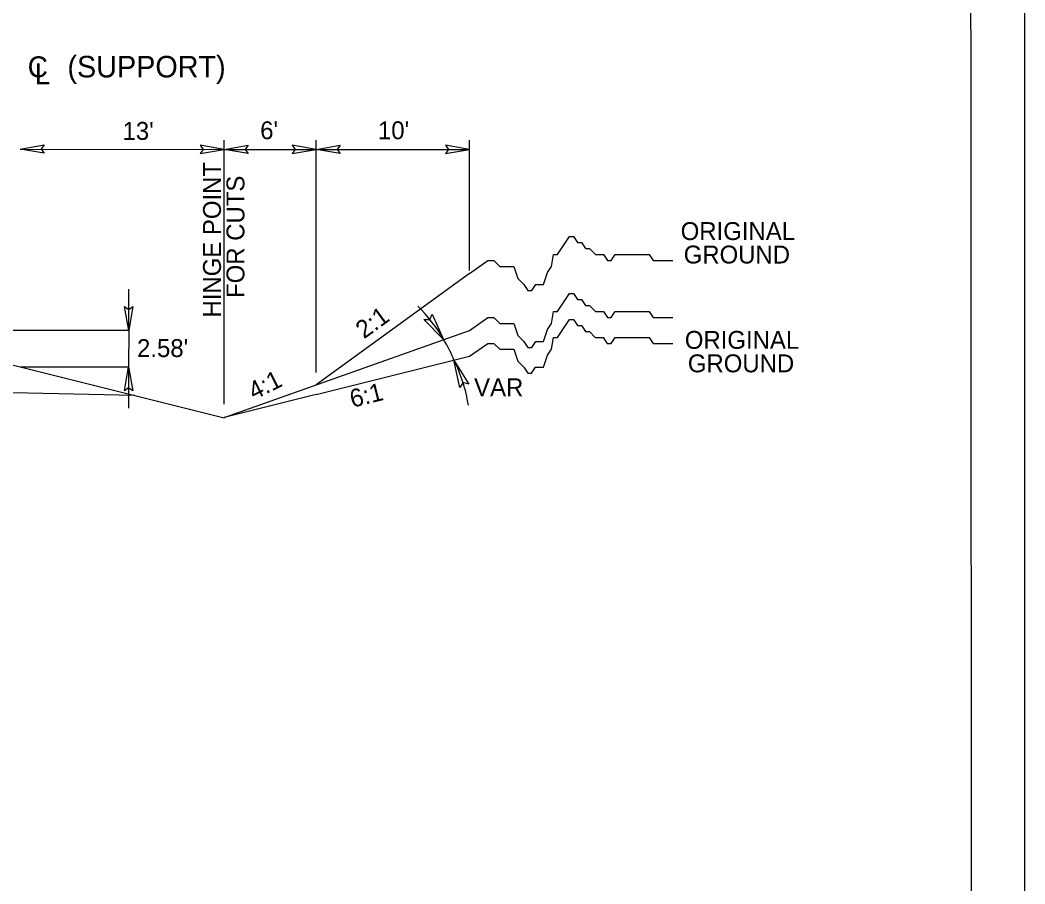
# Model space of a CAD drawing. Extents: x 1727387 to 1728895, y 539219 to 540208.
# Drawn here: x 1727645.2 to 1727723.8, y 539453.8 to 539521.4 of the extents above; entities that cross this region are included whole.
import ezdxf

# ---------------------------------------------------------------- set-up
doc = ezdxf.new("R2010")
doc.units = 0
for name, color, linetype in [('Default', 7, 'Continuous'), ('Overhead Sheet Border', 7, 'Continuous'), ('Prop Dimension Text', 7, 'Continuous'), ('Sheet Plot Border Outside CELL', 7, 'Continuous'), ('Typical Hinge Slope Interstate CELL', 7, 'Continuous'), ('Typical Pavement Slope CELL', 7, 'Continuous'), ('Typical Pavement Slope Information CELL', 7, 'Continuous'), ('Typical Text Centerline CELL', 7, 'Continuous')]:
    doc.layers.add(name, color=color, linetype=linetype)

msp = doc.modelspace()

# ---------------------------------------------------------------- linework, layer by layer
at = {"layer": 'Default'}
for p, q in [((1727645.155, 539511.289), (1727661.125, 539511.259)), ((1727661.126, 539511.259), (1727668.331, 539511.259)), ((1727661.133, 539491.314), (1727661.133, 539511.998)), ((1727668.331, 539511.259), (1727680.34, 539511.259)), ((1727668.339, 539493.807), (1727668.339, 539511.998)), ((1727680.347, 539501.785), (1727680.347, 539511.998)), ((1727653.656, 539497.076), (1727653.656, 539500.314)), ((1727653.649, 539497.076), (1727481.192, 539497.076)), ((1727653.656, 539497.076), (1727653.649, 539494.248)), ((1727645.155, 539494.248), (1727653.649, 539494.248)), ((1727653.649, 539494.248), (1727653.649, 539491.011))]:
    msp.add_line(p, q, dxfattribs=at)
for points in [[(1727647.034, 539510.966), (1727645.158, 539511.289), (1727647.044, 539511.623), (1727646.804, 539511.289)], [(1727659.258, 539510.937), (1727661.133, 539511.26), (1727659.247, 539511.593), (1727659.487, 539511.26)], [(1727663.009, 539510.937), (1727661.133, 539511.26), (1727663.019, 539511.593), (1727662.78, 539511.26)], [(1727666.463, 539510.937), (1727668.339, 539511.26), (1727666.453, 539511.593), (1727666.692, 539511.26)], [(1727670.214, 539510.937), (1727668.339, 539511.26), (1727670.225, 539511.593), (1727669.985, 539511.26)], [(1727678.464, 539510.936), (1727680.34, 539511.259), (1727678.454, 539511.592), (1727678.694, 539511.259)], [(1727653.984, 539498.951), (1727653.656, 539497.076), (1727653.327, 539498.963), (1727653.66, 539498.723)], [(1727677.404, 539498.363), (1727678.314, 539496.367), (1727676.772, 539497.947), (1727677.245, 539497.935)], [(1727679.588, 539492.617), (1727679.122, 539494.76), (1727680.294, 539492.89), (1727679.834, 539493.001)], [(1727679.588, 539492.617), (1727679.122, 539494.76), (1727680.294, 539492.89), (1727679.834, 539493.001)], [(1727653.326, 539492.373), (1727653.649, 539494.248), (1727653.983, 539492.362), (1727653.649, 539492.602)]]:
    msp.add_lwpolyline(points, close=True, dxfattribs=at)
at = {"layer": 'Overhead Sheet Border'}
msp.add_lwpolyline([(1727719.565, 539583.627), (1727419.828, 539583.466), (1727419.941, 539373.65), (1727719.678, 539373.811)], close=True, dxfattribs=at)
at = {"layer": 'Sheet Plot Border Outside CELL'}
msp.add_lwpolyline([(1727723.818, 539589.019), (1727387.253, 539589.019), (1727387.253, 539369.849), (1727723.818, 539369.849)], close=True, dxfattribs=at)
at = {"layer": 'Typical Hinge Slope Interstate CELL'}
for points in [[(1727680.34, 539501.55), (1727681.783, 539502.563), (1727682.251, 539502.563), (1727682.717, 539502.097), (1727683.029, 539502.097), (1727683.497, 539502.097), (1727683.808, 539502.097), (1727684.12, 539501.159), (1727684.587, 539500.694), (1727684.899, 539500.225), (1727685.21, 539500.225), (1727685.522, 539500.694), (1727685.833, 539500.694), (1727686.144, 539500.694), (1727686.456, 539501.628), (1727686.767, 539502.097), (1727686.924, 539503.032), (1727687.235, 539503.032), (1727687.547, 539503.497), (1727687.858, 539503.966), (1727688.169, 539504.435), (1727688.481, 539504.435), (1727688.792, 539503.966), (1727689.104, 539503.966), (1727689.415, 539503.497), (1727689.727, 539503.497), (1727690.194, 539503.032), (1727690.506, 539503.032), (1727690.817, 539503.032), (1727691.129, 539502.563), (1727691.44, 539502.563), (1727691.751, 539503.032), (1727692.063, 539503.032), (1727692.374, 539503.032), (1727692.686, 539503.032), (1727692.997, 539503.032), (1727693.465, 539503.032), (1727693.931, 539503.032), (1727694.399, 539503.032), (1727694.711, 539502.563), (1727695.177, 539502.563), (1727695.645, 539502.563), (1727696.268, 539502.563)], [(1727680.34, 539497.087), (1727681.783, 539498.1), (1727682.251, 539498.1), (1727682.717, 539497.635), (1727683.029, 539497.635), (1727683.497, 539497.635), (1727683.808, 539497.635), (1727684.12, 539496.697), (1727684.587, 539496.232), (1727684.899, 539495.763), (1727685.21, 539495.763), (1727685.522, 539496.232), (1727685.833, 539496.232), (1727686.144, 539496.232), (1727686.456, 539497.166), (1727686.767, 539497.635), (1727686.924, 539498.569), (1727687.235, 539498.569), (1727687.547, 539499.035), (1727687.858, 539499.504), (1727688.169, 539499.973), (1727688.481, 539499.973), (1727688.792, 539499.504), (1727689.104, 539499.504), (1727689.415, 539499.035), (1727689.727, 539499.035), (1727690.194, 539498.569), (1727690.506, 539498.569), (1727690.817, 539498.569), (1727691.129, 539498.1), (1727691.44, 539498.1), (1727691.751, 539498.569), (1727692.063, 539498.569), (1727692.374, 539498.569), (1727692.686, 539498.569), (1727692.997, 539498.569), (1727693.465, 539498.569), (1727693.931, 539498.569), (1727694.399, 539498.569), (1727694.711, 539498.1), (1727695.177, 539498.1), (1727695.645, 539498.1), (1727696.268, 539498.1)], [(1727680.333, 539495.063), (1727681.777, 539496.076), (1727682.244, 539496.076), (1727682.711, 539495.611), (1727683.022, 539495.611), (1727683.49, 539495.611), (1727683.802, 539495.611), (1727684.113, 539494.673), (1727684.581, 539494.207), (1727684.892, 539493.738), (1727685.204, 539493.738), (1727685.515, 539494.207), (1727685.827, 539494.207), (1727686.138, 539494.207), (1727686.449, 539495.142), (1727686.761, 539495.611), (1727686.917, 539496.545), (1727687.229, 539496.545), (1727687.54, 539497.01), (1727687.851, 539497.479), (1727688.163, 539497.948), (1727688.474, 539497.948), (1727688.786, 539497.479), (1727689.097, 539497.479), (1727689.409, 539497.01), (1727689.72, 539497.01), (1727690.188, 539496.545), (1727690.499, 539496.545), (1727690.811, 539496.545), (1727691.122, 539496.076), (1727691.434, 539496.076), (1727691.745, 539496.545), (1727692.056, 539496.545), (1727692.368, 539496.545), (1727692.679, 539496.545), (1727692.991, 539496.545), (1727693.458, 539496.545), (1727693.925, 539496.545), (1727694.393, 539496.545), (1727694.704, 539496.076), (1727695.171, 539496.076), (1727695.638, 539496.076), (1727696.261, 539496.076)]]:
    msp.add_lwpolyline(points, dxfattribs=at)
for centre, start, end in [((1727667.835, 539490.378), 29.75191, 45.50364), ((1727668.326, 539489.361), 8.9538, 26.57006), ((1727668.326, 539489.361), 8.9538, 26.57006)]:
    msp.add_arc(centre, 12.07, start, end, dxfattribs=at)
msp.add_ellipse((1727668.216, 539496.973), major_axis=(10.893, -5.199), ratio=0.5, start_param=0.463735, end_param=0.681536, dxfattribs=at)
at = {"layer": 'Typical Pavement Slope CELL'}
for p, q in [((1727680.34, 539501.55), (1727668.346, 539492.826)), ((1727661.122, 539490.26), (1727680.34, 539497.087)), ((1727639.512, 539495.659), (1727661.124, 539490.256)), ((1727668.326, 539492.061), (1727680.333, 539495.063)), ((1727654.117, 539492.008), (1727609.926, 539492.892)), ((1727668.326, 539492.061), (1727661.122, 539490.26))]:
    msp.add_line(p, q, dxfattribs=at)

# ---------------------------------------------------------------- texts
at = {"layer": 'Default'}
msp.add_text("2.58'", height=1.401, dxfattribs=at).set_placement((1727654.312, 539495.006))
at = {"layer": 'Prop Dimension Text'}
for s, p in [("6'", (1727663.952, 539512.059)), ("10'", (1727673.173, 539512.059)), ('ORIGINAL', (1727696.871, 539504.167)), ('GROUND', (1727697.107, 539502.33)), ('ORIGINAL', (1727697.195, 539495.649)), ('GROUND', (1727697.431, 539493.812)), ('VAR', (1727680.699, 539491.939))]:
    msp.add_text(s, height=1.401, dxfattribs=at).set_placement(p)
for s, height, rotation, p in [('HINGE POINT', 1.40103, 90, (1727660.88, 539498.1)), ('FOR CUTS', 1.401, 90, (1727662.716, 539499.633)), ('2:1', 1.401, 36.02984, (1727672.082, 539496.385)), ('4:1', 1.401, 26.57006, (1727663.467, 539491.618)), ('6:1', 1.401, 14.03809, (1727671.167, 539491.029))]:
    msp.add_text(s, height=height, rotation=rotation, dxfattribs=at).set_placement(p)
at = {"layer": 'Typical Pavement Slope Information CELL'}
msp.add_text("13'", height=1.401, dxfattribs=at).set_placement((1727653.177, 539512.011))
at = {"layer": 'Typical Text Centerline CELL'}
for s, height, rotation, p in [('C', 1.64, 0.04425, (1727645.752, 539516.907)), ('L', 1.641, 359.99115, (1727646.298, 539516.348))]:
    msp.add_text(s, height=height, rotation=rotation, dxfattribs=at).set_placement(p)
msp.add_text('(SUPPORT)', height=1.6842, dxfattribs=at).set_placement((1727648.863, 539516.9))

doc.saveas('drawing.dxf')
